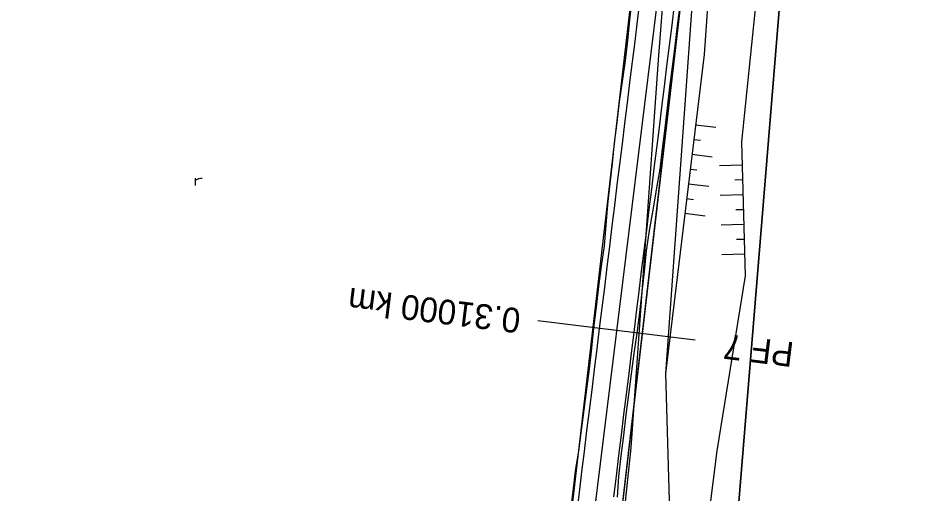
# Model space of a CAD drawing. Extents: x -555887 to -552101, y -1100251 to -1096546.
# Drawn here: x -553970.9 to -553879.9, y -1097893.2 to -1097845.2 of the extents above; entities that cross this region are included whole.
import ezdxf

# ---------------------------------------------------------------- set-up
doc = ezdxf.new("R2010")
doc.units = 0
for name, color, linetype in [('PARCELY_cesty', 7, 'Continuous'), ('PARCELY_VHO', 7, 'Continuous'), ('POLYGONY_SITUACE_PF', 7, 'Continuous'), ('POLYGONY_SITUACE_PF_POPISY', 7, 'Continuous'), ('POLYGONY_SITUACE_PO', 7, 'Continuous'), ('ZSST', 7, 'Continuous'), ('zájem', 7, 'Continuous')]:
    doc.layers.add(name, color=color, linetype=linetype)

msp = doc.modelspace()

# ---------------------------------------------------------------- linework, layer by layer
at = {"layer": 'PARCELY_cesty'}
for points in [[(-553910.622, -1097956.19), (-553913.42, -1097924.46), (-553903.498, -1097838.889), (-553902.803, -1097824.091), (-553903.199, -1097814.131), (-553905.076, -1097799.369), (-553911.111, -1097775.519), (-553924.494, -1097736.179), (-553926.037, -1097728.701), (-553926.88, -1097721.034), (-553927.942, -1097698.335), (-553927.014, -1097685.697), (-553927.851, -1097681.722), (-553929.538, -1097678.1), (-553932.003, -1097674.954), (-553935.116, -1097672.449), (-553938.716, -1097670.715), (-553942.616, -1097669.842), (-553946.468, -1097669.874), (-554027.52, -1097678.879), (-554030.91, -1097678.33)], [(-553915.615, -1097956.495), (-553918.446, -1097924.391), (-553908.484, -1097838.483), (-553907.808, -1097824.073), (-553908.187, -1097814.546), (-553909.998, -1097800.301), (-553915.909, -1097776.94), (-553929.328, -1097737.494), (-553930.981, -1097729.481), (-553931.867, -1097721.425), (-553932.951, -1097698.268), (-553932.053, -1097686.035), (-553932.625, -1097683.313), (-553933.828, -1097680.732), (-553935.584, -1097678.49), (-553937.803, -1097676.705), (-553940.369, -1097675.469), (-553943.148, -1097674.846), (-553946.14, -1097674.871), (-554026.66, -1097685.902), (-554029.64, -1097687.62)]]:
    msp.add_lwpolyline(points, dxfattribs=at)
at = {"layer": 'PARCELY_VHO'}
for points in [[(-553895.01, -1097951.32), (-553903.94, -1097924.64), (-553898.75, -1097900.98), (-553893.31, -1097834.53), (-553892.36, -1097818.14), (-553893.78, -1097805.84), (-553896.6, -1097785.6), (-553898.1, -1097777.85), (-553916.6, -1097732.86), (-553916.42, -1097704.51), (-553918.4, -1097676.29), (-553917.8, -1097670.8), (-553913.5, -1097649.75), (-553920.52, -1097625.16)], [(-553927.41, -1097628.08), (-553920.29, -1097651.1), (-553924.15, -1097670.8), (-553927.014, -1097685.697), (-553927.942, -1097698.335), (-553926.88, -1097721.034), (-553926.037, -1097728.701), (-553924.494, -1097736.179), (-553911.111, -1097775.519), (-553905.076, -1097799.369), (-553903.199, -1097814.131), (-553902.803, -1097824.091), (-553903.498, -1097838.889), (-553913.42, -1097924.2), (-553904.91, -1097952.6), (-553904.09, -1097966.52), (-553910.368, -1097974.94), (-553913.828, -1098111.034), (-553912.715, -1098125.988), (-553910.789, -1098134.707), (-553870.98, -1098223.96)]]:
    msp.add_lwpolyline(points, dxfattribs=at)
at = {"layer": 'POLYGONY_SITUACE_PF'}
for p, q in [((-553910.525, -1097876.722), (-553918.465, -1097875.742)), ((-553902.585, -1097877.702), (-553910.525, -1097876.722))]:
    msp.add_line(p, q, dxfattribs=at)
at = {"layer": 'POLYGONY_SITUACE_PO'}
for p, q in [((-553906.431, -1097843.542), (-553915.579, -1097917.677)), ((-553908.981, -1097843.326), (-553909.207, -1097845.398)), ((-553908.179, -1097843.425), (-553908.435, -1097845.493)), ((-553908.179, -1097843.425), (-553908.435, -1097845.493)), ((-553904.706, -1097843.854), (-553904.961, -1097845.922)), ((-553904.706, -1097843.854), (-553904.961, -1097845.922)), ((-553904.151, -1097843.923), (-553904.405, -1097845.99)), ((-553909.207, -1097845.398), (-553909.423, -1097847.47)), ((-553908.435, -1097845.493), (-553908.69, -1097847.561)), ((-553908.435, -1097845.493), (-553908.69, -1097847.561)), ((-553904.961, -1097845.922), (-553905.216, -1097847.989)), ((-553904.961, -1097845.922), (-553905.216, -1097847.989)), ((-553904.405, -1097845.99), (-553904.659, -1097848.058)), ((-553909.423, -1097847.47), (-553909.644, -1097849.542)), ((-553908.69, -1097847.561), (-553908.945, -1097849.628)), ((-553908.69, -1097847.561), (-553908.945, -1097849.628)), ((-553905.216, -1097847.989), (-553905.471, -1097850.057)), ((-553905.216, -1097847.989), (-553905.471, -1097850.057)), ((-553904.659, -1097848.058), (-553904.913, -1097850.126)), ((-553909.644, -1097849.542), (-553909.965, -1097851.602)), ((-553908.945, -1097849.628), (-553909.2, -1097851.696)), ((-553908.945, -1097849.628), (-553909.2, -1097851.696)), ((-553905.471, -1097850.057), (-553905.726, -1097852.125)), ((-553905.471, -1097850.057), (-553905.726, -1097852.125)), ((-553904.913, -1097850.126), (-553905.167, -1097852.194)), ((-553909.965, -1097851.602), (-553910.256, -1097853.665)), ((-553909.2, -1097851.696), (-553909.455, -1097853.764)), ((-553909.2, -1097851.696), (-553909.455, -1097853.764)), ((-553905.726, -1097852.125), (-553905.981, -1097854.192)), ((-553905.726, -1097852.125), (-553905.981, -1097854.192)), ((-553905.167, -1097852.194), (-553905.42, -1097854.262)), ((-553910.256, -1097853.665), (-553910.482, -1097855.736)), ((-553909.455, -1097853.764), (-553909.71, -1097855.831)), ((-553909.455, -1097853.764), (-553909.71, -1097855.831)), ((-553905.981, -1097854.192), (-553906.237, -1097856.26)), ((-553905.981, -1097854.192), (-553906.237, -1097856.26)), ((-553905.42, -1097854.262), (-553905.664, -1097856.331)), ((-553910.482, -1097855.736), (-553910.753, -1097857.802)), ((-553909.71, -1097855.831), (-553909.965, -1097857.899)), ((-553909.71, -1097855.831), (-553909.965, -1097857.899)), ((-553906.237, -1097856.26), (-553906.492, -1097858.328)), ((-553906.237, -1097856.26), (-553906.492, -1097858.328)), ((-553905.664, -1097856.331), (-553905.911, -1097858.399)), ((-553910.753, -1097857.802), (-553910.978, -1097859.873)), ((-553909.965, -1097857.899), (-553910.221, -1097859.967)), ((-553909.965, -1097857.899), (-553910.221, -1097859.967)), ((-553906.492, -1097858.328), (-553906.747, -1097860.395)), ((-553906.492, -1097858.328), (-553906.747, -1097860.395)), ((-553905.911, -1097858.399), (-553906.167, -1097860.467)), ((-553910.978, -1097859.873), (-553911.2, -1097861.945)), ((-553910.221, -1097859.967), (-553910.476, -1097862.034)), ((-553910.221, -1097859.967), (-553910.476, -1097862.034)), ((-553906.747, -1097860.395), (-553907.002, -1097862.463)), ((-553906.747, -1097860.395), (-553907.002, -1097862.463)), ((-553906.167, -1097860.467), (-553906.511, -1097862.523)), ((-553911.2, -1097861.945), (-553911.421, -1097864.017)), ((-553910.476, -1097862.034), (-553910.731, -1097864.102)), ((-553910.476, -1097862.034), (-553910.731, -1097864.102)), ((-553907.002, -1097862.463), (-553907.257, -1097864.531)), ((-553907.002, -1097862.463), (-553907.257, -1097864.531)), ((-553906.511, -1097862.523), (-553906.869, -1097864.578)), ((-553911.421, -1097864.017), (-553911.606, -1097866.093)), ((-553910.731, -1097864.102), (-553910.986, -1097866.17)), ((-553910.731, -1097864.102), (-553910.986, -1097866.17)), ((-553907.257, -1097864.531), (-553907.512, -1097866.598)), ((-553907.257, -1097864.531), (-553907.512, -1097866.598)), ((-553906.869, -1097864.578), (-553907.246, -1097866.631)), ((-553911.606, -1097866.093), (-553911.765, -1097868.173)), ((-553910.986, -1097866.17), (-553911.241, -1097868.237)), ((-553910.986, -1097866.17), (-553911.241, -1097868.237)), ((-553907.512, -1097866.598), (-553907.768, -1097868.666)), ((-553907.512, -1097866.598), (-553907.768, -1097868.666)), ((-553907.246, -1097866.631), (-553907.518, -1097868.697)), ((-553911.765, -1097868.173), (-553912.077, -1097870.233)), ((-553911.241, -1097868.237), (-553911.496, -1097870.305)), ((-553911.241, -1097868.237), (-553911.496, -1097870.305)), ((-553907.768, -1097868.666), (-553908.023, -1097870.733)), ((-553907.768, -1097868.666), (-553908.023, -1097870.733)), ((-553907.518, -1097868.697), (-553907.752, -1097870.767)), ((-553912.077, -1097870.233), (-553912.353, -1097872.298)), ((-553911.496, -1097870.305), (-553911.751, -1097872.372)), ((-553911.496, -1097870.305), (-553911.751, -1097872.372)), ((-553908.023, -1097870.733), (-553908.278, -1097872.801)), ((-553908.023, -1097870.733), (-553908.278, -1097872.801)), ((-553907.752, -1097870.767), (-553907.985, -1097872.837)), ((-553912.353, -1097872.298), (-553912.575, -1097874.37)), ((-553911.751, -1097872.372), (-553912.007, -1097874.44)), ((-553911.751, -1097872.372), (-553912.007, -1097874.44)), ((-553908.278, -1097872.801), (-553908.533, -1097874.869)), ((-553908.278, -1097872.801), (-553908.533, -1097874.869)), ((-553907.985, -1097872.837), (-553908.218, -1097874.908)), ((-553912.575, -1097874.37), (-553912.831, -1097876.438)), ((-553912.007, -1097874.44), (-553912.262, -1097876.508)), ((-553912.007, -1097874.44), (-553912.262, -1097876.508)), ((-553908.533, -1097874.869), (-553908.788, -1097876.936)), ((-553908.533, -1097874.869), (-553908.788, -1097876.936)), ((-553908.218, -1097874.908), (-553908.491, -1097876.973)), ((-553912.831, -1097876.438), (-553913.051, -1097878.509)), ((-553912.262, -1097876.508), (-553912.517, -1097878.575)), ((-553912.262, -1097876.508), (-553912.517, -1097878.575)), ((-553908.788, -1097876.936), (-553909.043, -1097879.004)), ((-553908.788, -1097876.936), (-553909.043, -1097879.004)), ((-553908.491, -1097876.973), (-553908.768, -1097879.038)), ((-553913.051, -1097878.509), (-553913.279, -1097880.58)), ((-553912.517, -1097878.575), (-553912.772, -1097880.643)), ((-553912.517, -1097878.575), (-553912.772, -1097880.643)), ((-553909.043, -1097879.004), (-553909.298, -1097881.072)), ((-553909.043, -1097879.004), (-553909.298, -1097881.072)), ((-553908.768, -1097879.038), (-553909.052, -1097881.102)), ((-553913.279, -1097880.58), (-553913.542, -1097882.647)), ((-553912.772, -1097880.643), (-553913.027, -1097882.711)), ((-553912.772, -1097880.643), (-553913.027, -1097882.711)), ((-553909.298, -1097881.072), (-553909.554, -1097883.139)), ((-553909.298, -1097881.072), (-553909.554, -1097883.139)), ((-553909.052, -1097881.102), (-553909.314, -1097883.169)), ((-553913.542, -1097882.647), (-553913.821, -1097884.712)), ((-553913.027, -1097882.711), (-553913.282, -1097884.778)), ((-553913.027, -1097882.711), (-553913.282, -1097884.778)), ((-553909.554, -1097883.139), (-553909.809, -1097885.207)), ((-553909.554, -1097883.139), (-553909.809, -1097885.207)), ((-553909.314, -1097883.169), (-553909.572, -1097885.236)), ((-553913.821, -1097884.712), (-553914.1, -1097886.777)), ((-553913.282, -1097884.778), (-553913.537, -1097886.846)), ((-553913.282, -1097884.778), (-553913.537, -1097886.846)), ((-553909.809, -1097885.207), (-553910.064, -1097887.275)), ((-553909.809, -1097885.207), (-553910.064, -1097887.275)), ((-553909.572, -1097885.236), (-553909.83, -1097887.304)), ((-553914.1, -1097886.777), (-553914.369, -1097888.843)), ((-553913.537, -1097886.846), (-553913.793, -1097888.914)), ((-553913.537, -1097886.846), (-553913.793, -1097888.914)), ((-553910.064, -1097887.275), (-553910.319, -1097889.342)), ((-553910.064, -1097887.275), (-553910.319, -1097889.342)), ((-553909.83, -1097887.304), (-553910.087, -1097889.371)), ((-553914.369, -1097888.843), (-553914.687, -1097890.902)), ((-553913.793, -1097888.914), (-553914.048, -1097890.981)), ((-553913.793, -1097888.914), (-553914.048, -1097890.981)), ((-553910.319, -1097889.342), (-553910.574, -1097891.41)), ((-553910.319, -1097889.342), (-553910.574, -1097891.41)), ((-553910.087, -1097889.371), (-553910.314, -1097891.442)), ((-553914.687, -1097890.902), (-553914.943, -1097892.97)), ((-553914.048, -1097890.981), (-553914.303, -1097893.049)), ((-553914.048, -1097890.981), (-553914.303, -1097893.049)), ((-553910.574, -1097891.41), (-553910.829, -1097893.478)), ((-553910.574, -1097891.41), (-553910.829, -1097893.478)), ((-553910.314, -1097891.442), (-553910.469, -1097893.522)), ((-553914.943, -1097892.97), (-553915.191, -1097895.039)), ((-553914.303, -1097893.049), (-553914.558, -1097895.117)), ((-553914.303, -1097893.049), (-553914.558, -1097895.117))]:
    msp.add_line(p, q, dxfattribs=at)
at = {"layer": 'ZSST'}
for p, q in [((-553902.558, -1097855.97), (-553900.51, -1097856.217)), ((-553902.738, -1097857.459), (-553902.056, -1097857.541)), ((-553902.918, -1097858.948), (-553900.87, -1097859.196)), ((-553903.098, -1097860.437), (-553902.416, -1097860.519)), ((-553897.854, -1097860.038), (-553900.157, -1097860.103)), ((-553903.278, -1097861.926), (-553901.23, -1097862.174)), ((-553897.812, -1097861.538), (-553898.579, -1097861.559)), ((-553897.77, -1097863.037), (-553900.073, -1097863.102)), ((-553903.458, -1097863.415), (-553902.776, -1097863.498)), ((-553903.638, -1097864.904), (-553901.591, -1097865.152)), ((-553897.728, -1097864.537), (-553898.495, -1097864.558)), ((-553897.686, -1097866.036), (-553899.988, -1097866.101)), ((-553897.643, -1097867.536), (-553898.41, -1097867.557)), ((-553897.601, -1097869.035), (-553899.904, -1097869.1))]:
    msp.add_line(p, q, dxfattribs=at)
for points in [[(-553924.66, -1097729.04), (-553921.53, -1097741.78), (-553916.02, -1097756.79), (-553908.51, -1097772.96), (-553902.81, -1097799.53), (-553901.3, -1097820.82), (-553903.22, -1097848.29), (-553905.59, -1097881.04), (-553905.22, -1097893.91), (-553907.85, -1097907.67), (-553911.16, -1097917.96), (-553910.53, -1097929.5), (-553905.13, -1097944.97), (-553902.46, -1097958.37), (-553903.33, -1097964.72)], [(-553920.88, -1097754.01), (-553919.13, -1097757.44), (-553911.89, -1097774.1), (-553904.85, -1097799.34), (-553904.03, -1097820.03), (-553906.32, -1097849.41), (-553909.08, -1097888.54)], [(-553908.51, -1097772.96), (-553901.02, -1097800.59), (-553899.7, -1097820.5), (-553901.7, -1097848.88), (-553905.59, -1097881.04)], [(-553894.87, -1097830.87), (-553895.44, -1097833.46), (-553897.92, -1097857.69), (-553897.54, -1097871.22), (-553900.41, -1097888.86), (-553902.99, -1097909.34), (-553907.18, -1097920.45), (-553905.9, -1097929.65), (-553896.22, -1097956.42), (-553897.58, -1097967.85)], [(-553952.978, -1097862.099), (-553952.978, -1097861.367)], [(-553952.978, -1097861.603), (-553952.876, -1097861.508), (-553952.773, -1097861.445), (-553952.616, -1097861.398), (-553952.466, -1097861.375), (-553952.309, -1097861.367)], [(-553909.08, -1097888.54), (-553912.97, -1097925.48), (-553908.5, -1097951.76), (-553912.35, -1097977.16), (-553914.28, -1098003.09), (-553915.41, -1098049.02)]]:
    msp.add_lwpolyline(points, dxfattribs=at)
at = {"layer": 'zájem'}
for points in [[(-553873.44, -1097756.54), (-553881.15, -1097737.32), (-553890.36, -1097670.23), (-553917.8, -1097670.8), (-553918.4, -1097676.29), (-553916.42, -1097704.51), (-553916.6, -1097732.86), (-553898.1, -1097777.85), (-553896.6, -1097785.6), (-553893.78, -1097805.84), (-553892.36, -1097818.14), (-553893.31, -1097834.53), (-553898.75, -1097900.98), (-553903.94, -1097924.64), (-553895.01, -1097951.32)], [(-553895.01, -1097951.32), (-553903.94, -1097924.64), (-553898.75, -1097900.98), (-553893.31, -1097834.53), (-553892.36, -1097818.14), (-553893.78, -1097805.84), (-553896.6, -1097785.6), (-553898.1, -1097777.85), (-553916.6, -1097732.86), (-553916.42, -1097704.51), (-553918.4, -1097676.29), (-553917.8, -1097670.8), (-553890.36, -1097670.23), (-553881.15, -1097737.32), (-553873.44, -1097756.54)]]:
    msp.add_lwpolyline(points, dxfattribs=at)

# ---------------------------------------------------------------- texts
at = {"layer": 'POLYGONY_SITUACE_PF_POPISY'}
for s, p in [('0.31000 km', (-553920.082, -1097874.535)), ('PF 7', (-553892.538, -1097877.934))]:
    msp.add_text(s, height=2.5, rotation=172.96527, dxfattribs=at).set_placement(p)

doc.saveas('drawing.dxf')
